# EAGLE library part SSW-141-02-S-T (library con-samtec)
THROUGH-HOLE .025" SQ POST SOCKET Source: Samtec SSW.pdf
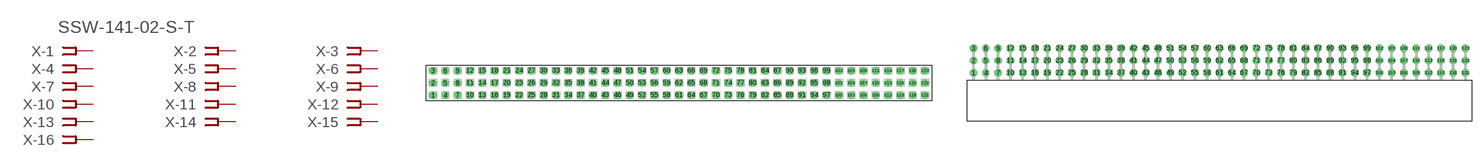
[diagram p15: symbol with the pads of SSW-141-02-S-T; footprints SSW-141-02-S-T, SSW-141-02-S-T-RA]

Designator prefix X; gates -1=FPINV -2=FPIN -3=FPIN -4=FPIN -5=FPIN -6=FPIN -7=FPIN -8=FPIN -9=FPIN -10=FPIN -11=FPIN -12=FPIN -13=FPIN -14=FPIN -15=FPIN -16=FPIN -17=FPIN -18=FPIN -19=FPIN -20=FPIN -21=FPIN -22=FPIN -23=FPIN -24=FPIN -25=FPIN -26=FPIN -27=FPIN -28=FPIN -29=FPIN -30=FPIN -31=FPIN -32=FPIN -33=FPIN -34=FPIN -35=FPIN -36=FPIN -37=FPIN -38=FPIN -39=FPIN -40=FPIN -41=FPIN -42=FPIN -43=FPIN -44=FPIN -45=FPIN -46=FPIN -47=FPIN -48=FPIN -49=FPIN -50=FPIN -51=FPIN -52=FPIN -53=FPIN -54=FPIN -55=FPIN -56=FPIN -57=FPIN -58=FPIN -59=FPIN -60=FPIN -61=FPIN -62=FPIN -63=FPIN -64=FPIN -65=FPIN -66=FPIN -67=FPIN -68=FPIN -69=FPIN -70=FPIN -71=FPIN -72=FPIN -73=FPIN -74=FPIN -75=FPIN -76=FPIN -77=FPIN -78=FPIN -79=FPIN -80=FPIN -81=FPIN -82=FPIN -83=FPIN -84=FPIN -85=FPIN -86=FPIN -87=FPIN -88=FPIN -89=FPIN -90=FPIN -91=FPIN -92=FPIN -93=FPIN -94=FPIN -95=FPIN -96=FPIN -97=FPIN -98=FPIN -99=FPIN -100=FPIN -101=FPIN -102=FPIN -103=FPIN -104=FPIN -105=FPIN -106=FPIN -107=FPIN -108=FPIN -109=FPIN -110=FPIN -111=FPIN -112=FPIN -113=FPIN -114=FPIN -115=FPIN -116=FPIN -117=FPIN -118=FPIN -119=FPIN -120=FPIN -121=FPIN -122=FPIN -123=FPIN

## SSW-141-02-S-T (OC_FARNELL: unknown; OC_NEWARK: unknown)  [SSW-141-02-S-T]
1  -1:1  pas
2  -2:1  pas
3  -3:1  pas
4  -4:1  pas
5  -5:1  pas
6  -6:1  pas
7  -7:1  pas
8  -8:1  pas
9  -9:1  pas
10  -10:1  pas
11  -11:1  pas
12  -12:1  pas
13  -13:1  pas
14  -14:1  pas
15  -15:1  pas
16  -16:1  pas
17  -17:1  pas
18  -18:1  pas
19  -19:1  pas
20  -20:1  pas
21  -21:1  pas
22  -22:1  pas
23  -23:1  pas
24  -24:1  pas
25  -25:1  pas
26  -26:1  pas
27  -27:1  pas
28  -28:1  pas
29  -29:1  pas
30  -30:1  pas
31  -31:1  pas
32  -32:1  pas
33  -33:1  pas
34  -34:1  pas
35  -35:1  pas
36  -36:1  pas
37  -37:1  pas
38  -38:1  pas
39  -39:1  pas
40  -40:1  pas
41  -41:1  pas
42  -42:1  pas
43  -43:1  pas
44  -44:1  pas
45  -45:1  pas
46  -46:1  pas
47  -47:1  pas
48  -48:1  pas
49  -49:1  pas
50  -50:1  pas
51  -51:1  pas
52  -52:1  pas
53  -53:1  pas
54  -54:1  pas
55  -55:1  pas
56  -56:1  pas
57  -57:1  pas
58  -58:1  pas
59  -59:1  pas
60  -60:1  pas
61  -61:1  pas
62  -62:1  pas
63  -63:1  pas
64  -64:1  pas
65  -65:1  pas
66  -66:1  pas
67  -67:1  pas
68  -68:1  pas
69  -69:1  pas
70  -70:1  pas
71  -71:1  pas
72  -72:1  pas
73  -73:1  pas
74  -74:1  pas
75  -75:1  pas
76  -76:1  pas
77  -77:1  pas
78  -78:1  pas
79  -79:1  pas
80  -80:1  pas
81  -81:1  pas
82  -82:1  pas
83  -83:1  pas
84  -84:1  pas
85  -85:1  pas
86  -86:1  pas
87  -87:1  pas
88  -88:1  pas
89  -89:1  pas
90  -90:1  pas
91  -91:1  pas
92  -92:1  pas
93  -93:1  pas
94  -94:1  pas
95  -95:1  pas
96  -96:1  pas
97  -97:1  pas
98  -98:1  pas
99  -99:1  pas
100  -100:1  pas
101  -101:1  pas
102  -102:1  pas
103  -103:1  pas
104  -104:1  pas
105  -105:1  pas
106  -106:1  pas
107  -107:1  pas
108  -108:1  pas
109  -109:1  pas
110  -110:1  pas
111  -111:1  pas
112  -112:1  pas
113  -113:1  pas
114  -114:1  pas
115  -115:1  pas
116  -116:1  pas
117  -117:1  pas
118  -118:1  pas
119  -119:1  pas
120  -120:1  pas
121  -121:1  pas
122  -122:1  pas
123  -123:1  pas

## SSW-141-02-S-TRA (OC_FARNELL: unknown; OC_NEWARK: unknown)  [SSW-141-02-S-T-RA]
Pads as for SSW-141-02-S-T

## Footprint SSW-141-02-S-T (pad centres in mm)
THROUGH-HOLE .025" SQ POST SOCKET Source: Samtec SSW.pdf
drill 1 pad 1.5 octagon: 1 -50.8,-2.54; 2 -50.8,0; 3 -50.8,2.54; 4 -48.26,-2.54; 5 -48.26,0; 6 -48.26,2.54; 7 -45.72,-2.54; 8 -45.72,0; 9 -45.72,2.54; 10 -43.18,-2.54; 11 -43.18,0; 12 -43.18,2.54; 13 -40.64,-2.54; 14 -40.64,0; 15 -40.64,2.54; 16 -38.1,-2.54; 17 -38.1,0; 18 -38.1,2.54; 19 -35.56,-2.54; 20 -35.56,0; 21 -35.56,2.54; 22 -33.02,-2.54; 23 -33.02,0; 24 -33.02,2.54; 25 -30.48,-2.54; 26 -30.48,0; 27 -30.48,2.54; 28 -27.94,-2.54; 29 -27.94,0; 30 -27.94,2.54; 31 -25.4,-2.54; 32 -25.4,0; 33 -25.4,2.54; 34 -22.86,-2.54; 35 -22.86,0; 36 -22.86,2.54; 37 -20.32,-2.54; 38 -20.32,0; 39 -20.32,2.54; 40 -17.78,-2.54; 41 -17.78,0; 42 -17.78,2.54; 43 -15.24,-2.54; 44 -15.24,0; 45 -15.24,2.54; 46 -12.7,-2.54; 47 -12.7,0; 48 -12.7,2.54; 49 -10.16,-2.54; 50 -10.16,0; 51 -10.16,2.54; 52 -7.62,-2.54; 53 -7.62,0; 54 -7.62,2.54; 55 -5.08,-2.54; 56 -5.08,0; 57 -5.08,2.54; 58 -2.54,-2.54; 59 -2.54,0; 60 -2.54,2.54; 61 0,-2.54; 62 0,0; 63 0,2.54; 64 2.54,-2.54; 65 2.54,0; 66 2.54,2.54; 67 5.08,-2.54; 68 5.08,0; 69 5.08,2.54; 70 7.62,-2.54; 71 7.62,0; 72 7.62,2.54; 73 10.16,-2.54; 74 10.16,0; 75 10.16,2.54; 76 12.7,-2.54; 77 12.7,0; 78 12.7,2.54; 79 15.24,-2.54; 80 15.24,0; 81 15.24,2.54; 82 17.78,-2.54; 83 17.78,0; 84 17.78,2.54; 85 20.32,-2.54; 86 20.32,0; 87 20.32,2.54; 88 22.86,-2.54; 89 22.86,0; 90 22.86,2.54; 91 25.4,-2.54; 92 25.4,0; 93 25.4,2.54; 94 27.94,-2.54; 95 27.94,0; 96 27.94,2.54; 97 30.48,-2.54; 98 30.48,0; 99 30.48,2.54; 100 33.02,-2.54; 101 33.02,0; 102 33.02,2.54; 103 35.56,-2.54; 104 35.56,0; 105 35.56,2.54; 106 38.1,-2.54; 107 38.1,0; 108 38.1,2.54; 109 40.64,-2.54; 110 40.64,0; 111 40.64,2.54; 112 43.18,-2.54; 113 43.18,0; 114 43.18,2.54; 115 45.72,-2.54; 116 45.72,0; 117 45.72,2.54; 118 48.26,-2.54; 119 48.26,0; 120 48.26,2.54; 121 50.8,-2.54; 122 50.8,0; 123 50.8,2.54

## Footprint SSW-141-02-S-T-RA (pad centres in mm)
THROUGH-HOLE .025" SQ POST SOCKET Source: Samtec SSW.pdf
drill 1 pad 1.5 octagon: 1 -50.8,1.524; 2 -50.8,4.064; 3 -50.8,6.604; 4 -48.26,1.524; 5 -48.26,4.064; 6 -48.26,6.604; 7 -45.72,1.524; 8 -45.72,4.064; 9 -45.72,6.604; 10 -43.18,1.524; 11 -43.18,4.064; 12 -43.18,6.604; 13 -40.64,1.524; 14 -40.64,4.064; 15 -40.64,6.604; 16 -38.1,1.524; 17 -38.1,4.064; 18 -38.1,6.604; 19 -35.56,1.524; 20 -35.56,4.064; 21 -35.56,6.604; 22 -33.02,1.524; 23 -33.02,4.064; 24 -33.02,6.604; 25 -30.48,1.524; 26 -30.48,4.064; 27 -30.48,6.604; 28 -27.94,1.524; 29 -27.94,4.064; 30 -27.94,6.604; 31 -25.4,1.524; 32 -25.4,4.064; 33 -25.4,6.604; 34 -22.86,1.524; 35 -22.86,4.064; 36 -22.86,6.604; 37 -20.32,1.524; 38 -20.32,4.064; 39 -20.32,6.604; 40 -17.78,1.524; 41 -17.78,4.064; 42 -17.78,6.604; 43 -15.24,1.524; 44 -15.24,4.064; 45 -15.24,6.604; 46 -12.7,1.524; 47 -12.7,4.064; 48 -12.7,6.604; 49 -10.16,1.524; 50 -10.16,4.064; 51 -10.16,6.604; 52 -7.62,1.524; 53 -7.62,4.064; 54 -7.62,6.604; 55 -5.08,1.524; 56 -5.08,4.064; 57 -5.08,6.604; 58 -2.54,1.524; 59 -2.54,4.064; 60 -2.54,6.604; 61 0,1.524; 62 0,4.064; 63 0,6.604; 64 2.54,1.524; 65 2.54,4.064; 66 2.54,6.604; 67 5.08,1.524; 68 5.08,4.064; 69 5.08,6.604; 70 7.62,1.524; 71 7.62,4.064; 72 7.62,6.604; 73 10.16,1.524; 74 10.16,4.064; 75 10.16,6.604; 76 12.7,1.524; 77 12.7,4.064; 78 12.7,6.604; 79 15.24,1.524; 80 15.24,4.064; 81 15.24,6.604; 82 17.78,1.524; 83 17.78,4.064; 84 17.78,6.604; 85 20.32,1.524; 86 20.32,4.064; 87 20.32,6.604; 88 22.86,1.524; 89 22.86,4.064; 90 22.86,6.604; 91 25.4,1.524; 92 25.4,4.064; 93 25.4,6.604; 94 27.94,1.524; 95 27.94,4.064; 96 27.94,6.604; 97 30.48,1.524; 98 30.48,4.064; 99 30.48,6.604; 100 33.02,1.524; 101 33.02,4.064; 102 33.02,6.604; 103 35.56,1.524; 104 35.56,4.064; 105 35.56,6.604; 106 38.1,1.524; 107 38.1,4.064; 108 38.1,6.604; 109 40.64,1.524; 110 40.64,4.064; 111 40.64,6.604; 112 43.18,1.524; 113 43.18,4.064; 114 43.18,6.604; 115 45.72,1.524; 116 45.72,4.064; 117 45.72,6.604; 118 48.26,1.524; 119 48.26,4.064; 120 48.26,6.604; 121 50.8,1.524; 122 50.8,4.064; 123 50.8,6.604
